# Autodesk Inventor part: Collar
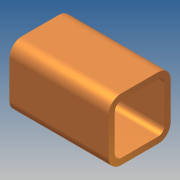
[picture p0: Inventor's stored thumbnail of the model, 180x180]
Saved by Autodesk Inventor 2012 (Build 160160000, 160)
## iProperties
Created: 2007-12
Part Number: Collar
Document SubType Name: Modeling
Designer: MJ
Material: Aluminum-6061
Stock Number: D-623-009-a
Density: 2.71 g/cm^3
Engineer: MJ
Mass: 371.09 g
Surface Area: 458.242 cm^2
Volume: 136.934 cm^3
RuleStatus: InUse
Title: DgPr Assembly Cell
Author: MJ
Comments: 2" X 2" X 1/8" WALL TUBE X 4"
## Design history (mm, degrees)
sketch "Sketch2"
  geometry: L1 (-19.05, -31.75)-(19.05, -31.75); L2 (31.75, -19.05)-(31.75, 19.05); L3 (19.05, 31.75)-(-19.05, 31.75); L4 (-31.75, 19.05)-(-31.75, -19.05); L5 (-25.4, 19.05)-(-25.4, -19.05); L6 (-19.05, -25.4)-(19.05, -25.4); L7 (25.4, -19.05)-(25.4, 19.05); L8 (19.05, 25.4)-(-19.05, 25.4); A1 r 12.7 centre (19.05, 19.05) between (31.75, 19.05) and (19.05, 31.75); A2 r 12.7 centre (-19.05, 19.05) between (-19.05, 31.75) and (-31.75, 19.05); A3 r 12.7 centre (-19.05, -19.05) between (-31.75, -19.05) and (-19.05, -31.75); A4 r 12.7 centre (19.05, -19.05) between (19.05, -31.75) and (31.75, -19.05); A5 r 6.35 centre (-19.05, 19.05) between (-19.05, 25.4) and (-25.4, 19.05); A6 r 6.35 centre (-19.05, -19.05) between (-25.4, -19.05) and (-19.05, -25.4); A7 r 6.35 centre (19.05, -19.05) between (19.05, -25.4) and (25.4, -19.05); A8 r 6.35 centre (19.05, 19.05) between (25.4, 19.05) and (19.05, 25.4); 6 further points
  constraints: 16 end point, 16 point on circle, 8 centre point, 8 tangent, 6 point on line, 5 parallel, 3 equal radius, 2 horizontal alignment, 2 midpoint, 2 perpendicular, 2 vertical alignment, 1 horizontal, 8 other
extrude "Extrusion1" new body sketch "Sketch2" taper "d5" = 0 deg
body "Solid1"
